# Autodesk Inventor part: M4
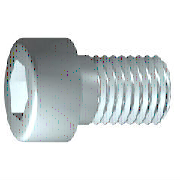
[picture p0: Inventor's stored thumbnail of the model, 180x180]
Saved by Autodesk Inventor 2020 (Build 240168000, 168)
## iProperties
Created: 2016-04
Part Number: M4
Material: 강철, 연강
Description: 6각머리 태핑 나사
Document SubType Name: Modeling
Standard: KS B 1003
Designer: mdu
Standards Organization: KS
Language: ko-KR
Size Designation: M 4 x 10
Categories: <MemberInstance><Categories><Category DisplayName="조임쇠" InternalName="e4da775c-781d-43d5-af7c-5136215cf5a6" Mnemonic="FSTN"><Category DisplayName="볼트" InternalN
Density: 7.86 g/cm^3
Mass: 2.0371 g
Surface Area: 3.0572 cm^2
Volume: 0.259174 cm^3
Appearance: 강철
IsCustomPart: 0
Author: mdu
Revision Number: 1
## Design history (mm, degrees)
sketch "스케치1"
  geometry: L1 (-1, 0)-(10, 0); L2 (10, 0)-(10, 2); L3 (10, 2)-(1.75, 2); L4 (1.75, 2)-(1.32, 2); L5 (1.32, 2)-(0, 2); L6 (0, 2)-(0, 3.5); L7 (0, 3.5)-(-4, 3.5); L8 (-4, 3.5)-(-4, 1.732); L9 (-4, 1.732)-(-2, 1.732); L10 (-2, 1.732)-(-1, 0); L11 (-6.8, 0)-(12.8, 0) reference; L12 (0, -0.7)-(0, 4.2) reference; L13 (1.75, 2)-(0, 2)
  constraints: 22 end point, 6 parallel, 2 collinear, 2 perpendicular, 1 horizontal, 1 point on line
  dimensions: "d1" = 8.25 distance from line of L3.end L2 (= GEL); "d2" = 0.42952 distance of L4.end L3.end (computed from GAL); "d3" = 4 distance between parallel lines of L8 L6 (= KOH); "d4" = 2 distance of L8.end L9.end (= INTI); "d5" = 60 deg angle of L10 L1; "d6" = 4 diameter of L3 L1 (= GD); "d7" = 4 diameter of L5 L1 (= BDM); "d8" = 3.4641 diameter of L9 L1 (= 1.1547 x SW); "d9" = 7 diameter of L7 L1 (= KOD); "d26" = 10 distance between parallel lines of L12 L2 (= NLG)
revolve "본체" sketch "스케치1" stored, may be unused: angle "d10" = 90 deg
sketch "스케치2"
  geometry: L1 (0, -4.9)-(0, 4.9) reference; L2 (-4.9, 0)-(4.9, 0) reference; L3 (1.732, 0)-(0.866, -1.5); L4 (0.866, -1.5)-(-0.866, -1.5); L5 (-0.866, -1.5)-(-1.732, 0); L6 (-1.732, 0)-(-0.866, 1.5); L7 (-0.866, 1.5)-(0.866, 1.5); L8 (0.866, 1.5)-(1.732, 0); 2 further points
  constraints: 12 end point, 1 coincident, 1 horizontal alignment, 1 point on line, 12 other
extrude "슬롯" join sketch "스케치2" stored distance "d11" = 10; taper "d12" = 0 deg
workplane "Work Plane1"
fillet "Fillet2" dims "d30" = 0.1 (= R)
body "Solid1"
fillet "모깎기1" dims "d17" = 0.4 (= RR)
feature "스레드" dims "d13" = 8.25 (= GEL), "d14" = 0
chamfer "모따기1" distance "d15" = 0.42941 (= -0.5 x SPD + 0.5 x GD); stored, may be unused: second distance "d16" = 0.42941 (= GUL), angle "d27" = 45 deg
other parameters: "GD" = 4 (= NND) [user parameter; used in 2 equation terms], "NLG" = 10 [user parameter; used in 1 equation term], "GEL" = 8.25 [user parameter; used in 2 equation terms], "KOD" = 7 [user parameter; used in 1 equation term], "KOH" = 4 [user parameter; used in 1 equation term], "INTI" = 2 [user parameter; used in 1 equation term], "GAL" = 0.42941 (= 0.61345 x PTC) [user parameter; used in 1 equation term], "GUL" = 0.42941 (= 0.61345 x PTC) [user parameter; used in 1 equation term], "BDM" = 4 (= NND) [user parameter; used in 1 equation term], "SW" = 3 [user parameter; used in 2 equation terms], "RR" = 0.4 [user parameter; used in 1 equation term], "SPD" = 3.14117 (= NND - 1.2269 x PTC) [user parameter; used in 1 equation term], "d19" = 0, "d28" = 0, "d29" = 0, "R" = 0.1 [user parameter; used in 1 equation term], "PHH" = 0.2 [user parameter], "GD1" = 3.14117 (= THREADDIA - 1.2269 x PTC) [user parameter], "THREADDIA" = 4 [user parameter; used in 1 equation term], "FAWI" = 45 deg [user parameter], "TPU" = 14.28571 (computed from PTC) [user parameter], "PTC" = 0.7 [user parameter; used in 5 equation terms], "NND" = 4 [user parameter; used in 3 equation terms], "TOA" = 30 deg [user parameter], "E0" = 3.465 (= 1.155 x SW) [user parameter]
